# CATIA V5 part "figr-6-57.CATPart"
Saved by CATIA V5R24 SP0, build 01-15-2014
Part number: Part1
Bounding box of the stored display mesh (mm): x -50.648 to 69.574, y -72.183 to 91.11, z 0 to 52
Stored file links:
  D:\KAVITA\CATIA V5-6R2014 Project_ Kavita\CATIA V5-6R2014_partfiles\Partfiles\c06_catia_v5-6r2014_prt\figr-6-57.CATPart
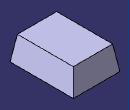
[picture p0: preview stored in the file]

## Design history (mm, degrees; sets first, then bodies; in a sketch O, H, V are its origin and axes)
Body1 (main body)
  Sketch1 on xy-plane, origin (0, 0, 0), H (1, 0, 0), V (0, 1, 0)
    line L1 (-50.6478, 72.1832) -> (50.6478, 72.1832)
    line L2 (50.6478, 72.1832) -> (50.6478, -72.1832)
    line L3 (50.6478, -72.1832) -> (-50.6478, -72.1832)
    line L4 (-50.6478, -72.1832) -> (-50.6478, 72.1832)
    axis line L5 (50.6478, -72.1832) -> (-50.6478, 72.1832)
    horizontal: L1 H, L3 H
    vertical: L2 V, L4 V
    midpoint: O L5
  Pad1: profile Sketch1, direction (0, 0, 1), length 52
  Draft1: Angle 20, Neutral face of Pad1, PullDir edge [face of Pad1 | face of Pad1], SupportToDraft (face of Pad1; face of Pad1)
